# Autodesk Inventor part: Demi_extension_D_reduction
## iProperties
Shininess: 64.0
Length Units: 11269
Angle Units: 11279
Time Units: 11290
Mass Units: 11283
Length Display Precision: 3
Angle Display Precision: 2
Compacted: True
Part Number: Demi_extension_D_reduction
Document SubType Name: Modeling
Created: 2008-02
Material: Acier inoxydable, austénitique
Designer: Pascal
Density: 0.0
Volumn: 0.0
Area: 0.0
PropertySet Name: Model Information
Control State: 0
Master: False
Checked Out: False
MATIERE_PIECE: X2CrNi 18-11
OBSERVATIONS: Tôle ep. 15/10
DESIGNATION: Demi-extension droite
Author: Pascal
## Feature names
1. Extrusion1
2. Extrusion2
3. Extrusion3
